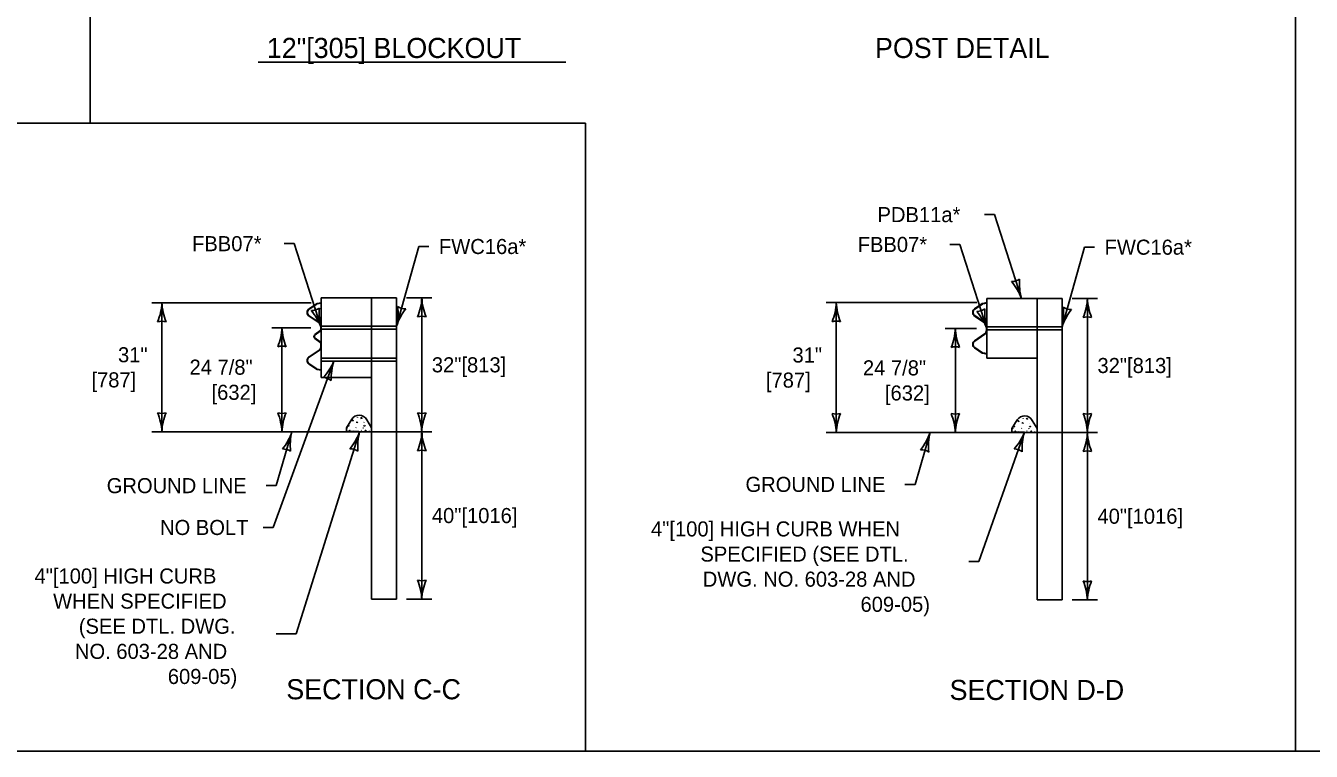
# Model space of a CAD drawing. Extents: x 49991 to 50160, y 49948 to 50051.
# Drawn here: x 50005.88 to 50011, y 49987.8 to 49990.69 of the extents above; entities that cross this region are included whole.
import ezdxf

# ---------------------------------------------------------------- set-up
doc = ezdxf.new("R2010")
doc.units = 0
for name, color, linetype in [('Default', 7, 'Continuous'), ('Level 1', 7, 'Continuous'), ('Level 2', 7, 'Continuous'), ('Level 3', 7, 'Continuous'), ('Level 4', 7, 'Continuous')]:
    doc.layers.add(name, color=color, linetype=linetype)

msp = doc.modelspace()

# ---------------------------------------------------------------- linework, layer by layer
at = {"layer": 'Default'}
for p, q in [((50009.6594, 49989.5606), (50009.6892, 49989.5808)), ((50009.6604, 49989.5592), (50009.6902, 49989.5793)), ((50009.6921, 49989.5819), (50009.708, 49989.5848)), ((50009.6924, 49989.5802), (50009.7083, 49989.5831)), ((50009.7083, 49989.5831), (50009.708, 49989.5848)), ((50009.6993, 49989.5047), (50009.6594, 49989.5316)), ((50009.7002, 49989.5062), (50009.6604, 49989.5331)), ((50009.6746, 49989.5235), (50009.6733, 49989.5223)), ((50007.0573, 49989.4786), (50007.0573, 49989.4786)), ((50007.0574, 49989.4793), (50007.0574, 49989.491)), ((50009.7062, 49989.4733), (50009.7062, 49989.4917)), ((50009.708, 49989.4733), (50009.708, 49989.4917)), ((50007.0316, 49989.4548), (50007.0336, 49989.457)), ((50007.0574, 49989.4205), (50007.0574, 49989.4196)), ((50007.0574, 49989.4069), (50007.0574, 49989.4185)), ((50009.6594, 49989.4333), (50009.6993, 49989.4602)), ((50009.6604, 49989.4319), (50009.7002, 49989.4588)), ((50007.0573, 49989.4065), (50007.0574, 49989.4069)), ((50009.6892, 49989.3842), (50009.6594, 49989.4043)), ((50009.6902, 49989.3856), (50009.6604, 49989.4058)), ((50009.6689, 49989.4), (50009.6677, 49989.3988)), ((50009.708, 49989.3801), (50009.6921, 49989.383)), ((50009.7083, 49989.3818), (50009.6924, 49989.3848)), ((50009.7083, 49989.3818), (50009.708, 49989.3801)), ((50007.0375, 49989.3226), (50007.0365, 49989.324)), ((50007.0574, 49989.3158), (50007.0577, 49989.3175))]:
    msp.add_line(p, q, dxfattribs=at)
for points in [[(50007.0574, 49989.491), (50007.0573, 49989.4917), (50007.0573, 49989.4917)], [(50007.0573, 49989.4786), (50007.0574, 49989.479), (50007.0574, 49989.4793)], [(50007.0574, 49989.4185), (50007.0573, 49989.4194), (50007.0573, 49989.4196)]]:
    msp.add_lwpolyline(points, dxfattribs=at)
for centre, radius, start, end in [((50009.6934, 49989.5746), 0.00744, 100.4285, 124.048), ((50009.6934, 49989.5746), 0.00569, 100.4285, 124.048), ((50009.6692, 49989.5461), 0.0175, 124.048, 235.952), ((50009.6692, 49989.5461), 0.0157, 124.048, 235.952), ((50009.6905, 49989.4917), 0.0157, 0, 55.952), ((50009.6905, 49989.4733), 0.0157, 304.048, 0), ((50009.6905, 49989.4917), 0.0175, 0, 55.952), ((50009.6905, 49989.4733), 0.0175, 304.048, 0), ((50009.6692, 49989.4188), 0.0175, 124.048, 235.952), ((50009.6692, 49989.4188), 0.0157, 124.048, 235.952), ((50009.6934, 49989.3904), 0.00744, 235.952, 259.5715), ((50009.6934, 49989.3904), 0.00569, 235.952, 259.5715)]:
    msp.add_arc(centre, radius, start, end, dxfattribs=at)
at = {"layer": 'Level 1'}
for p, q in [((49999.3835, 49990.2991), (50008.1103, 49990.2991)), ((50008.1103, 49990.2991), (50008.1103, 49987.7988)), ((50007.0386, 49989.5801), (50007.0088, 49989.56)), ((50007.0396, 49989.5786), (50007.0098, 49989.5585)), ((50007.0375, 49989.5772), (50007.0365, 49989.5786)), ((50007.0574, 49989.5842), (50007.0415, 49989.5813)), ((50007.0577, 49989.5825), (50007.0418, 49989.5795)), ((50007.0574, 49989.5842), (50007.0552, 49989.582)), ((50007.0574, 49989.604), (50007.2574, 49989.604)), ((50007.0574, 49989.604), (50007.0574, 49989.2873)), ((50007.0577, 49989.5825), (50007.0574, 49989.5842)), ((50007.2574, 49988.404), (50007.2574, 49989.604)), ((50007.2574, 49989.604), (50007.3574, 49989.604)), ((50007.2574, 49989.604), (50007.2574, 49989.2873)), ((50007.3574, 49988.404), (50007.3574, 49989.604)), ((50009.6594, 49989.5606), (50009.6892, 49989.5808)), ((50009.6604, 49989.5592), (50009.6902, 49989.5793)), ((50009.6921, 49989.5819), (50009.708, 49989.5848)), ((50009.6924, 49989.5802), (50009.7083, 49989.5831)), ((50009.708, 49989.6012), (50009.908, 49989.6012)), ((50009.708, 49989.3637), (50009.708, 49989.6012)), ((50009.7083, 49989.5831), (50009.708, 49989.5848)), ((50009.908, 49988.4012), (50009.908, 49989.6012)), ((50009.908, 49989.6012), (50010.008, 49989.6012)), ((50009.908, 49989.3637), (50009.908, 49989.6012)), ((50010.008, 49988.4012), (50010.008, 49989.6012)), ((50007.0075, 49989.5343), (50007.0063, 49989.5331)), ((50007.0088, 49989.531), (50007.0487, 49989.504)), ((50007.0098, 49989.5324), (50007.0497, 49989.5055)), ((50007.0244, 49989.5684), (50007.0234, 49989.5698)), ((50007.0244, 49989.5226), (50007.0234, 49989.5211)), ((50009.6993, 49989.5047), (50009.6594, 49989.5316)), ((50009.7002, 49989.5062), (50009.6604, 49989.5331)), ((50009.6746, 49989.5235), (50009.6733, 49989.5223)), ((50007.0322, 49989.4577), (50007.0521, 49989.4721)), ((50007.0535, 49989.4713), (50007.0336, 49989.457)), ((50007.0375, 49989.5137), (50007.0365, 49989.5123)), ((50007.0425, 49989.5104), (50007.0412, 49989.5091)), ((50007.0556, 49989.4917), (50007.0573, 49989.4917)), ((50007.0556, 49989.4793), (50007.0556, 49989.491)), ((50007.0574, 49989.4884), (50007.0556, 49989.4884)), ((50007.0573, 49989.4786), (50007.0556, 49989.4786)), ((50009.7062, 49989.4733), (50009.7062, 49989.4917)), ((50009.708, 49989.4733), (50009.708, 49989.4917)), ((50007.0521, 49989.4279), (50007.0322, 49989.4423)), ((50007.0336, 49989.443), (50007.0535, 49989.4286)), ((50007.0556, 49989.4205), (50007.0556, 49989.4196)), ((50007.0556, 49989.4196), (50007.0574, 49989.4196)), ((50007.0556, 49989.4069), (50007.0556, 49989.4185)), ((50009.6594, 49989.4333), (50009.6993, 49989.4602)), ((50009.6604, 49989.4319), (50009.7002, 49989.4588)), ((50007.0487, 49989.3959), (50007.0088, 49989.369)), ((50007.0098, 49989.3676), (50007.0497, 49989.3945)), ((50007.0564, 49989.4065), (50007.055, 49989.405)), ((50007.0572, 49989.4065), (50007.0554, 49989.4065)), ((50007.0556, 49989.4069), (50007.0556, 49989.4065)), ((50007.0572, 49989.4065), (50007.0573, 49989.4065)), ((50009.6892, 49989.3842), (50009.6594, 49989.4043)), ((50009.6902, 49989.3856), (50009.6604, 49989.4058)), ((50009.6689, 49989.4), (50009.6677, 49989.3988)), ((50009.708, 49989.3801), (50009.6921, 49989.383)), ((50009.7083, 49989.3818), (50009.6924, 49989.3848)), ((50009.7083, 49989.3818), (50009.708, 49989.3801)), ((50007.0031, 49989.3531), (50007.0014, 49989.3515)), ((50007.0088, 49989.34), (50007.0386, 49989.3199)), ((50007.0396, 49989.3213), (50007.0098, 49989.3415)), ((50007.034, 49989.3251), (50007.0328, 49989.3239)), ((50007.0574, 49989.3158), (50007.0415, 49989.3187)), ((50007.0418, 49989.3205), (50007.0577, 49989.3175)), ((50009.708, 49989.3637), (50009.908, 49989.3637)), ((50007.0574, 49989.2873), (50007.2574, 49989.2873)), ((50007.1574, 49989.0867), (50007.1787, 49989.1206)), ((50007.2016, 49989.1271), (50007.2021, 49989.1263)), ((50007.2385, 49989.1189), (50007.2574, 49989.0867)), ((50009.808, 49989.0839), (50009.8293, 49989.1178)), ((50009.8522, 49989.1243), (50009.8527, 49989.1235)), ((50009.8891, 49989.1162), (50009.908, 49989.0839)), ((50007.1574, 49989.0726), (50007.1574, 49989.0867)), ((50007.1574, 49989.0726), (50007.2574, 49989.0706)), ((50007.1605, 49989.0862), (50007.161, 49989.0854)), ((50007.161, 49989.0859), (50007.1616, 49989.0851)), ((50007.1849, 49989.0733), (50007.1855, 49989.0745)), ((50007.1957, 49989.0862), (50007.1963, 49989.0874)), ((50007.2074, 49989.0716), (50007.2074, 49989.0716)), ((50007.2074, 49989.0716), (50007.2074, 49989.0716)), ((50007.2165, 49989.0764), (50007.2171, 49989.0776)), ((50007.2244, 49989.0862), (50007.225, 49989.0854)), ((50007.225, 49989.0859), (50007.2255, 49989.0851)), ((50007.2272, 49989.1072), (50007.2278, 49989.1084)), ((50007.2275, 49989.0932), (50007.2287, 49989.0957)), ((50007.2475, 49989.1017), (50007.248, 49989.1028)), ((50007.2488, 49989.0733), (50007.2494, 49989.0745)), ((50007.2574, 49989.0706), (50007.2574, 49989.0867)), ((50009.808, 49989.0699), (50009.808, 49989.0839)), ((50009.808, 49989.0699), (50009.908, 49989.0679)), ((50009.8111, 49989.0835), (50009.8116, 49989.0827)), ((50009.8116, 49989.0832), (50009.8122, 49989.0824)), ((50009.8355, 49989.0705), (50009.8361, 49989.0717)), ((50009.8463, 49989.0835), (50009.8469, 49989.0847)), ((50009.858, 49989.0689), (50009.858, 49989.0689)), ((50009.858, 49989.0689), (50009.858, 49989.0689)), ((50009.8671, 49989.0736), (50009.8677, 49989.0748)), ((50009.875, 49989.0835), (50009.8755, 49989.0827)), ((50009.8755, 49989.0832), (50009.8761, 49989.0824)), ((50009.8778, 49989.1044), (50009.8783, 49989.1056)), ((50009.8781, 49989.0904), (50009.8793, 49989.093)), ((50009.8981, 49989.099), (50009.8986, 49989.1)), ((50009.8994, 49989.0705), (50009.9, 49989.0717)), ((50009.908, 49989.0679), (50009.908, 49989.0839)), ((50007.2574, 49988.404), (50007.3574, 49988.404)), ((50009.908, 49988.4012), (50010.008, 49988.4012))]:
    msp.add_line(p, q, dxfattribs=at)
msp.add_lwpolyline([(49999.3835, 49998.9992), (50016.7501, 49998.9992), (50016.7501, 49987.7988), (49999.3835, 49987.7988)], close=True, dxfattribs=at)
for points in [[(50006.1377, 49990.2991), (50006.1377, 49993.358), (49999.3835, 49993.358)], [(50006.1377, 49993.358), (50010.9365, 49993.358), (50010.9365, 49987.7988)], [(50007.0521, 49989.4721), (50007.0533, 49989.4732), (50007.0542, 49989.4745), (50007.0549, 49989.4759), (50007.0554, 49989.4774), (50007.0556, 49989.4785), (50007.0556, 49989.4786)], [(50007.0573, 49989.4786), (50007.0572, 49989.4775), (50007.0566, 49989.4756), (50007.0558, 49989.474), (50007.0547, 49989.4725), (50007.0541, 49989.4719), (50007.0535, 49989.4713)], [(50007.0556, 49989.491), (50007.0556, 49989.4917), (50007.0556, 49989.4917)], [(50007.0556, 49989.4793), (50007.0556, 49989.4787), (50007.0556, 49989.4786)], [(50007.0322, 49989.4423), (50007.0309, 49989.4435), (50007.0298, 49989.4449), (50007.0291, 49989.4464), (50007.0286, 49989.4479), (50007.0284, 49989.4495), (50007.0284, 49989.4512), (50007.0288, 49989.4528), (50007.0294, 49989.4543), (50007.0302, 49989.4557), (50007.0313, 49989.4569), (50007.0322, 49989.4577)], [(50007.0336, 49989.457), (50007.033, 49989.4565), (50007.0324, 49989.4559), (50007.0319, 49989.4553), (50007.0314, 49989.4545), (50007.031, 49989.4537), (50007.0307, 49989.4531), (50007.0305, 49989.4525), (50007.0303, 49989.4518), (50007.0302, 49989.4509), (50007.0301, 49989.4502), (50007.0301, 49989.4496), (50007.0302, 49989.4488), (50007.0305, 49989.4476), (50007.0308, 49989.4467), (50007.0311, 49989.446), (50007.0315, 49989.4452), (50007.0319, 49989.4446), (50007.0323, 49989.4442), (50007.0328, 49989.4437), (50007.0336, 49989.443)], [(50007.0556, 49989.4205), (50007.0554, 49989.4223), (50007.0549, 49989.4242), (50007.0542, 49989.4256), (50007.0531, 49989.4269), (50007.0527, 49989.4274), (50007.0521, 49989.4279)], [(50007.0535, 49989.4286), (50007.0549, 49989.4272), (50007.0561, 49989.4255), (50007.0568, 49989.4239), (50007.0572, 49989.4222), (50007.0573, 49989.4213), (50007.0574, 49989.4205)], [(50007.0556, 49989.4196), (50007.0556, 49989.4192), (50007.0556, 49989.4185)], [(50007.0088, 49989.34), (50007.0077, 49989.3409), (50007.0066, 49989.3418), (50007.0056, 49989.3429), (50007.0046, 49989.3441), (50007.0032, 49989.3462), (50007.0025, 49989.3478), (50007.0019, 49989.3493), (50007.0014, 49989.3518), (50007.0012, 49989.3536), (50007.0012, 49989.3551), (50007.0014, 49989.3577), (50007.0018, 49989.3594), (50007.0023, 49989.3609), (50007.0031, 49989.3625), (50007.0038, 49989.3638), (50007.0044, 49989.3647), (50007.0054, 49989.3659), (50007.0064, 49989.367), (50007.0072, 49989.3678), (50007.0088, 49989.369)], [(50007.0098, 49989.3676), (50007.0078, 49989.3659), (50007.006, 49989.3639), (50007.0046, 49989.3617), (50007.0036, 49989.3592), (50007.003, 49989.3566), (50007.0029, 49989.354), (50007.0032, 49989.3513), (50007.004, 49989.3488), (50007.0051, 49989.3464), (50007.0067, 49989.3443), (50007.0082, 49989.3428), (50007.0098, 49989.3415)], [(50007.0487, 49989.3959), (50007.0502, 49989.3971), (50007.0516, 49989.3985), (50007.0532, 49989.4006), (50007.0544, 49989.4029), (50007.0554, 49989.4065)], [(50007.0572, 49989.4065), (50007.0568, 49989.4047), (50007.0559, 49989.4019), (50007.0545, 49989.3993), (50007.0526, 49989.397), (50007.0505, 49989.3951), (50007.0497, 49989.3945)], [(50007.181, 49989.1141), (50007.1826, 49989.1174), (50007.1852, 49989.1154), (50007.181, 49989.1141)], [(50007.2156, 49989.1236), (50007.2172, 49989.1269), (50007.2199, 49989.1249), (50007.2156, 49989.1236)], [(50009.8315, 49989.1113), (50009.8331, 49989.1147), (50009.8358, 49989.1127), (50009.8315, 49989.1113)], [(50009.8662, 49989.1209), (50009.8678, 49989.1242), (50009.8705, 49989.1222), (50009.8662, 49989.1209)], [(50007.1636, 49989.0932), (50007.1652, 49989.0965), (50007.1679, 49989.0945), (50007.1636, 49989.0932)], [(50007.1684, 49989.0724), (50007.1705, 49989.0765), (50007.1724, 49989.0723)], [(50007.199, 49989.1059), (50007.1995, 49989.1097), (50007.2032, 49989.1059)], [(50007.2302, 49989.0957), (50007.2318, 49989.0945), (50007.2275, 49989.0932)], [(50007.2316, 49989.0712), (50007.2344, 49989.0765), (50007.2369, 49989.071)], [(50009.8142, 49989.0904), (50009.8158, 49989.0938), (50009.8184, 49989.0918), (50009.8142, 49989.0904)], [(50009.819, 49989.0697), (50009.8211, 49989.0737), (50009.823, 49989.0696)], [(50009.8496, 49989.1032), (50009.8501, 49989.107), (50009.8538, 49989.1032)], [(50009.8808, 49989.093), (50009.8823, 49989.0918), (50009.8781, 49989.0904)], [(50009.8822, 49989.0684), (50009.885, 49989.0737), (50009.8874, 49989.0683)]]:
    msp.add_lwpolyline(points, dxfattribs=at)
for centre, radius, start, end in [((50007.0428, 49989.5739), 0.00744, 100.4285, 124.048), ((50007.0428, 49989.5739), 0.00569, 100.4285, 124.048), ((50009.6934, 49989.5746), 0.00744, 100.4285, 124.048), ((50009.6934, 49989.5746), 0.00569, 100.4285, 124.048), ((50007.0186, 49989.5455), 0.0175, 124.048, 235.952), ((50007.0186, 49989.5455), 0.0157, 124.048, 235.952), ((50009.6692, 49989.5461), 0.0175, 124.048, 235.952), ((50009.6692, 49989.5461), 0.0157, 124.048, 235.952), ((50007.0399, 49989.491), 0.0157, 2.6292, 55.952), ((50007.0399, 49989.491), 0.0175, 2.3659, 55.952), ((50009.6905, 49989.4917), 0.0157, 0, 55.952), ((50009.6905, 49989.4733), 0.0157, 304.048, 0), ((50009.6905, 49989.4917), 0.0175, 0, 55.952), ((50009.6905, 49989.4733), 0.0175, 304.048, 0), ((50009.6692, 49989.4188), 0.0175, 124.048, 235.952), ((50009.6692, 49989.4188), 0.0157, 124.048, 235.952), ((50009.6934, 49989.3904), 0.00744, 235.952, 259.5715), ((50009.6934, 49989.3904), 0.00569, 235.952, 259.5715), ((50007.0428, 49989.326), 0.00744, 235.9564, 259.5671), ((50007.0428, 49989.326), 0.00569, 235.9564, 259.5671), ((50007.2081, 49989.1012), 0.0352, 30.1855, 146.6195), ((50009.8587, 49989.0985), 0.0352, 30.1855, 146.6195)]:
    msp.add_arc(centre, radius, start, end, dxfattribs=at)
at = {"layer": 'Level 2'}
msp.add_line((50006.8069, 49990.5427), (50008.0315, 49990.5427), dxfattribs=at)
at = {"layer": 'Level 3'}
for p, q in [((50009.738, 49989.9352), (50009.698, 49989.9352)), ((50009.8458, 49989.6012), (50009.738, 49989.9352)), ((50006.9495, 49989.8196), (50006.9095, 49989.8196)), ((50007.0574, 49989.4857), (50006.9495, 49989.8196)), ((50007.3574, 49989.4915), (50007.4462, 49989.8083)), ((50007.4462, 49989.8083), (50007.4862, 49989.8083)), ((50009.6001, 49989.8164), (50009.5601, 49989.8164)), ((50009.708, 49989.4825), (50009.6001, 49989.8164)), ((50010.008, 49989.4887), (50010.0968, 49989.8056)), ((50010.0968, 49989.8056), (50010.1368, 49989.8056)), ((50007.0174, 49989.5842), (50006.3827, 49989.5842)), ((50006.4227, 49989.5842), (50006.4227, 49989.0706)), ((50007.3974, 49989.604), (50007.4979, 49989.604)), ((50007.4579, 49989.0706), (50007.4579, 49989.604)), ((50009.668, 49989.5848), (50009.0685, 49989.5848)), ((50009.1085, 49989.0679), (50009.1085, 49989.5848)), ((50010.048, 49989.6012), (50010.1485, 49989.6012)), ((50010.1085, 49989.0679), (50010.1085, 49989.6012)), ((50007.0156, 49989.4851), (50006.8609, 49989.4851)), ((50006.9009, 49989.4851), (50006.9009, 49989.0706)), ((50009.6662, 49989.4825), (50009.5425, 49989.4825)), ((50009.5825, 49989.0679), (50009.5825, 49989.4825)), ((50007.1076, 49989.3519), (50006.8664, 49988.6898)), ((50006.3827, 49989.0706), (50007.4979, 49989.0706)), ((50006.9403, 49989.0706), (50006.8784, 49988.8563)), ((50007.2101, 49989.0706), (50006.9577, 49988.2666)), ((50007.4579, 49989.0706), (50007.4579, 49988.404)), ((50009.0685, 49989.0679), (50010.1485, 49989.0679)), ((50009.4817, 49989.0679), (50009.422, 49988.8612)), ((50009.858, 49989.0689), (50009.6761, 49988.554)), ((50010.1085, 49989.0679), (50010.1085, 49988.4012)), ((50006.8784, 49988.8563), (50006.8384, 49988.8563)), ((50009.422, 49988.8612), (50009.382, 49988.8612)), ((50006.8664, 49988.6898), (50006.8264, 49988.6898)), ((50009.6761, 49988.554), (50009.6361, 49988.554)), ((50007.3974, 49988.404), (50007.4979, 49988.404)), ((50010.048, 49988.4012), (50010.1485, 49988.4012)), ((50006.9177, 49988.2666), (50006.8777, 49988.2666)), ((50006.9577, 49988.2666), (50006.9177, 49988.2666))]:
    msp.add_line(p, q, dxfattribs=at)
for centre, radius, start, end in [((50009.8064, 49989.7232), 0.0548, 270.0345, 305.7569), ((50010.06, 49989.6608), 0.2223, 175.3517, 195.5352), ((50009.6279, 49989.5188), 0.233, 20.723, 39.9729), ((50006.2006, 49989.5933), 0.2223, 337.456, 357.6395), ((50006.6555, 49989.5957), 0.233, 182.8273, 202.0772), ((50007.2358, 49989.6131), 0.2223, 337.456, 357.6395), ((50007.6907, 49989.6155), 0.233, 182.8273, 202.0772), ((50008.8864, 49989.594), 0.2223, 337.456, 357.6395), ((50009.3412, 49989.5963), 0.233, 182.8273, 202.0772), ((50009.8864, 49989.6104), 0.2223, 337.456, 357.6395), ((50010.3412, 49989.6127), 0.233, 182.8273, 202.0772), ((50007.018, 49989.6077), 0.0548, 270.0345, 305.7569), ((50006.8394, 49989.4032), 0.233, 20.723, 39.9729), ((50007.2716, 49989.5452), 0.2223, 175.3517, 195.5352), ((50007.1302, 49989.5433), 0.233, 347.164, 6.4139), ((50007.5688, 49989.4227), 0.2223, 141.7927, 161.9762), ((50007.392, 49989.6149), 0.0548, 236.4755, 272.1979), ((50007.4579, 49989.4758), 0.0548, 72.1388, 107.8612), ((50009.6686, 49989.6045), 0.0548, 270.0345, 305.7569), ((50009.49, 49989.4), 0.233, 20.723, 39.9729), ((50009.9221, 49989.542), 0.2223, 175.3517, 195.5352), ((50009.7808, 49989.5405), 0.233, 347.164, 6.4139), ((50010.2194, 49989.42), 0.2223, 141.7927, 161.9762), ((50010.0426, 49989.6122), 0.0548, 236.4755, 272.1979), ((50010.1085, 49989.473), 0.0548, 72.1388, 107.8612), ((50006.4227, 49989.456), 0.0548, 72.1388, 107.8612), ((50006.6788, 49989.4943), 0.2223, 337.456, 357.6395), ((50007.1337, 49989.4966), 0.233, 182.8273, 202.0772), ((50009.1085, 49989.4566), 0.0548, 72.1388, 107.8612), ((50009.3604, 49989.4916), 0.2223, 337.456, 357.6395), ((50009.8152, 49989.494), 0.233, 182.8273, 202.0772), ((50006.9009, 49989.3569), 0.0548, 72.1388, 107.8612), ((50009.5825, 49989.3543), 0.0548, 72.1388, 107.8612), ((50006.902, 49989.4365), 0.2223, 317.441, 337.6245), ((50007.3302, 49989.283), 0.233, 162.8123, 182.0622), ((50007.0637, 49989.2314), 0.0548, 52.1238, 87.8462), ((50006.4227, 49989.1989), 0.0548, 252.1388, 287.8612), ((50006.19, 49989.0591), 0.233, 2.8273, 22.0772), ((50006.6449, 49989.0615), 0.2223, 157.456, 177.6395), ((50006.9009, 49989.1989), 0.0548, 252.1388, 287.8612), ((50006.6682, 49989.0591), 0.233, 2.8273, 22.0772), ((50007.1231, 49989.0615), 0.2223, 157.456, 177.6395), ((50007.4579, 49989.1989), 0.0548, 252.1388, 287.8612), ((50007.2252, 49989.0591), 0.233, 2.8273, 22.0772), ((50007.6801, 49989.0615), 0.2223, 157.456, 177.6395), ((50009.1085, 49989.1961), 0.0548, 252.1388, 287.8612), ((50008.8758, 49989.0564), 0.233, 2.8273, 22.0772), ((50009.3306, 49989.0587), 0.2223, 157.456, 177.6395), ((50009.5825, 49989.1961), 0.0548, 252.1388, 287.8612), ((50009.3498, 49989.0564), 0.233, 2.8273, 22.0772), ((50009.8046, 49989.0587), 0.2223, 157.456, 177.6395), ((50010.1085, 49989.1961), 0.0548, 252.1388, 287.8612), ((50009.8758, 49989.0564), 0.233, 2.8273, 22.0772), ((50010.3307, 49989.0587), 0.2223, 157.456, 177.6395), ((50006.7295, 49989.1411), 0.2223, 321.3407, 341.5242), ((50007.1671, 49989.0171), 0.233, 166.712, 185.9619), ((50007.0009, 49989.1459), 0.2223, 320.03, 340.2135), ((50007.4356, 49989.0119), 0.233, 165.4013, 184.6512), ((50007.2358, 49989.0798), 0.2223, 337.456, 357.6395), ((50007.6907, 49989.0821), 0.233, 182.8273, 202.0772), ((50009.2708, 49989.1383), 0.2223, 321.3407, 341.5242), ((50009.7085, 49989.0143), 0.233, 166.712, 185.9619), ((50009.6516, 49989.1515), 0.2223, 318.0037, 338.1872), ((50010.0812, 49989.0022), 0.233, 163.375, 182.6248), ((50009.8864, 49989.077), 0.2223, 337.456, 357.6395), ((50010.3412, 49989.0794), 0.233, 182.8273, 202.0772), ((50006.9048, 49988.9475), 0.0548, 56.0235, 91.7459), ((50007.1717, 49988.9483), 0.0548, 54.7128, 90.4352), ((50007.4579, 49988.9424), 0.0548, 72.1388, 107.8612), ((50009.4461, 49988.9447), 0.0548, 56.0235, 91.7459), ((50009.8153, 49988.948), 0.0548, 52.6865, 88.4089), ((50010.1085, 49988.9397), 0.0548, 72.1388, 107.8612), ((50007.4579, 49988.5322), 0.0548, 252.1388, 287.8612), ((50007.2252, 49988.3925), 0.233, 2.8273, 22.0772), ((50007.6801, 49988.3948), 0.2223, 157.456, 177.6395), ((50010.1085, 49988.5294), 0.0548, 252.1388, 287.8612), ((50009.8758, 49988.3897), 0.233, 2.8273, 22.0772), ((50010.3307, 49988.3921), 0.2223, 157.456, 177.6395)]:
    msp.add_arc(centre, radius, start, end, dxfattribs=at)
at = {"layer": 'Level 4'}
for p, q in [((50007.3574, 49989.4915), (50007.0574, 49989.4915)), ((50007.3574, 49989.479), (50007.0574, 49989.479)), ((50010.008, 49989.4887), (50009.708, 49989.4887)), ((50010.008, 49989.4762), (50009.708, 49989.4762)), ((50007.3574, 49989.3644), (50007.0574, 49989.3644)), ((50007.3574, 49989.3519), (50007.0574, 49989.3519))]:
    msp.add_line(p, q, dxfattribs=at)

# ---------------------------------------------------------------- texts
at = {"layer": 'Level 2'}
for s, height, p in [('12"[305] BLOCKOUT', 0.08, (50006.8408, 49990.5587)), ('POST DETAIL', 0.08, (50009.2626, 49990.5587)), ('PDB11a*', 0.06, (50009.2726, 49989.9052)), ('FBB07*', 0.06, (50006.543, 49989.7896)), ('FWC16a*', 0.06, (50007.5262, 49989.7783)), ('FBB07*', 0.06, (50009.1936, 49989.7864)), ('FWC16a*', 0.06, (50010.1768, 49989.7756)), ('31"', 0.06, (50006.2482, 49989.3474)), ('32"[813]', 0.06, (50007.4979, 49989.3073)), ('31"', 0.06, (50008.934, 49989.3464)), ('32"[813]', 0.06, (50010.1485, 49989.3046)), ('24 7/8"', 0.06, (50006.5329, 49989.2979)), ('24 7/8"', 0.06, (50009.2145, 49989.2952)), ('[787]', 0.06, (50006.1423, 49989.2474)), ('[787]', 0.06, (50008.8281, 49989.2464)), ('[632]', 0.06, (50006.6205, 49989.1979)), ('[632]', 0.06, (50009.3021, 49989.1952)), ('GROUND LINE', 0.06, (50006.2032, 49988.8263)), ('GROUND LINE', 0.06, (50008.7468, 49988.8312)), ('40"[1016]', 0.06, (50007.4979, 49988.7073)), ('40"[1016]', 0.06, (50010.1485, 49988.7046)), ('NO BOLT', 0.06, (50006.4154, 49988.6598)), ('4"[100] HIGH CURB WHEN ', 0.06, (50008.3707, 49988.654)), ('SPECIFIED (SEE DTL. ', 0.06, (50008.5673, 49988.554)), ('4"[100] HIGH CURB', 0.06, (50005.9157, 49988.4666)), ('DWG. NO. 603-28 AND ', 0.06, (50008.5768, 49988.454)), ('WHEN SPECIFIED ', 0.06, (50005.9896, 49988.3666)), ('609-05) ', 0.06, (50009.2049, 49988.354)), ('(SEE DTL. DWG. ', 0.06, (50006.092, 49988.2666)), ('NO. 603-28 AND ', 0.06, (50006.0765, 49988.1666)), ('609-05) ', 0.06, (50006.4465, 49988.0666)), ('SECTION C-C', 0.08, (50006.9182, 49988.0058)), ('SECTION D-D', 0.08, (50009.5596, 49988.003))]:
    msp.add_text(s, height=height, dxfattribs=at).set_placement(p)

doc.saveas('drawing.dxf')
